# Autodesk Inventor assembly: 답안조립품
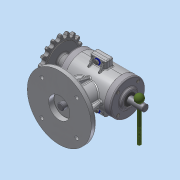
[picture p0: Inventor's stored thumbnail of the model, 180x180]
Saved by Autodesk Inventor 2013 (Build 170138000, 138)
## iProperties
Created: 2016-04
Part Number: 답안조립품
Document SubType Name: Assembly
Designer: dgall
Mass: 1745.72 g
Surface Area: 1440.72 cm^2
Volume: 462.011 cm^3
Density: 3.77854 g/cm^3
Author: dgall
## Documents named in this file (19)
- C:\Users\dgall\Desktop\360407V1010\답안조립품.iam
- C:\Users\dgall\Desktop\360407V1010\본체.ipt
- C:\Users\dgall\Desktop\360407V1010\본체상부커버.ipt
- C:\Users\dgall\Desktop\360407V1010\볼트 M4 x 16.ipt
- C:\Users\dgall\Desktop\360407V1010\뒤커버.ipt
- C:\Users\dgall\Desktop\360407V1010\베어링 6202.ipt
- C:\Users\dgall\Desktop\360407V1010\앞커버.ipt
- C:\Users\dgall\Desktop\360407V1010\베어링 6201.ipt
- C:\Users\dgall\Desktop\360407V1010\편심축.ipt
- C:\Users\dgall\Desktop\360407V1010\키 4 x 4 x 18.ipt
- C:\Users\dgall\Desktop\360407V1010\오일실 12 22 7.ipt
- C:\Users\dgall\Desktop\360407V1010\와셔 ST 4-100.ipt
- C:\Users\dgall\Desktop\360407V1010\너트 M4.ipt
- C:\Users\dgall\Desktop\360407V1010\볼트 M3x0.5x8.ipt
- C:\Users\dgall\Desktop\360407V1010\스프로킷.ipt
- C:\Users\dgall\Desktop\360407V1010\멈춤나사 M3x8.ipt
- C:\Users\dgall\Desktop\360407V1010\슬라이드.ipt
- C:\Users\dgall\Desktop\360407V1010\레바.ipt
- C:\Users\dgall\Desktop\360407V1010\스프링 - [가변].ipt
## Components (6 placed, 3 different names)
1. ISO 4762 M4 x 16:1
2. ISO 4762 M4 x 16:2
3. ISO 7091 ST 4 - 100 HV:1
4. ISO 7091 ST 4 - 100 HV:2
5. ISO 4032 M4:1
6. ISO 4032 M4:2
